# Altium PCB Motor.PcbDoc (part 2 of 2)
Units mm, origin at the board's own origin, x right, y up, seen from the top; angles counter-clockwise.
Board outline 48.64 x 60.2 mm, 4 copper layers (Top Layer, VCC, GND, Bottom Layer), stack 0.778 mm thick; 131 components, 120 nets, 670 pads, 289 vias.
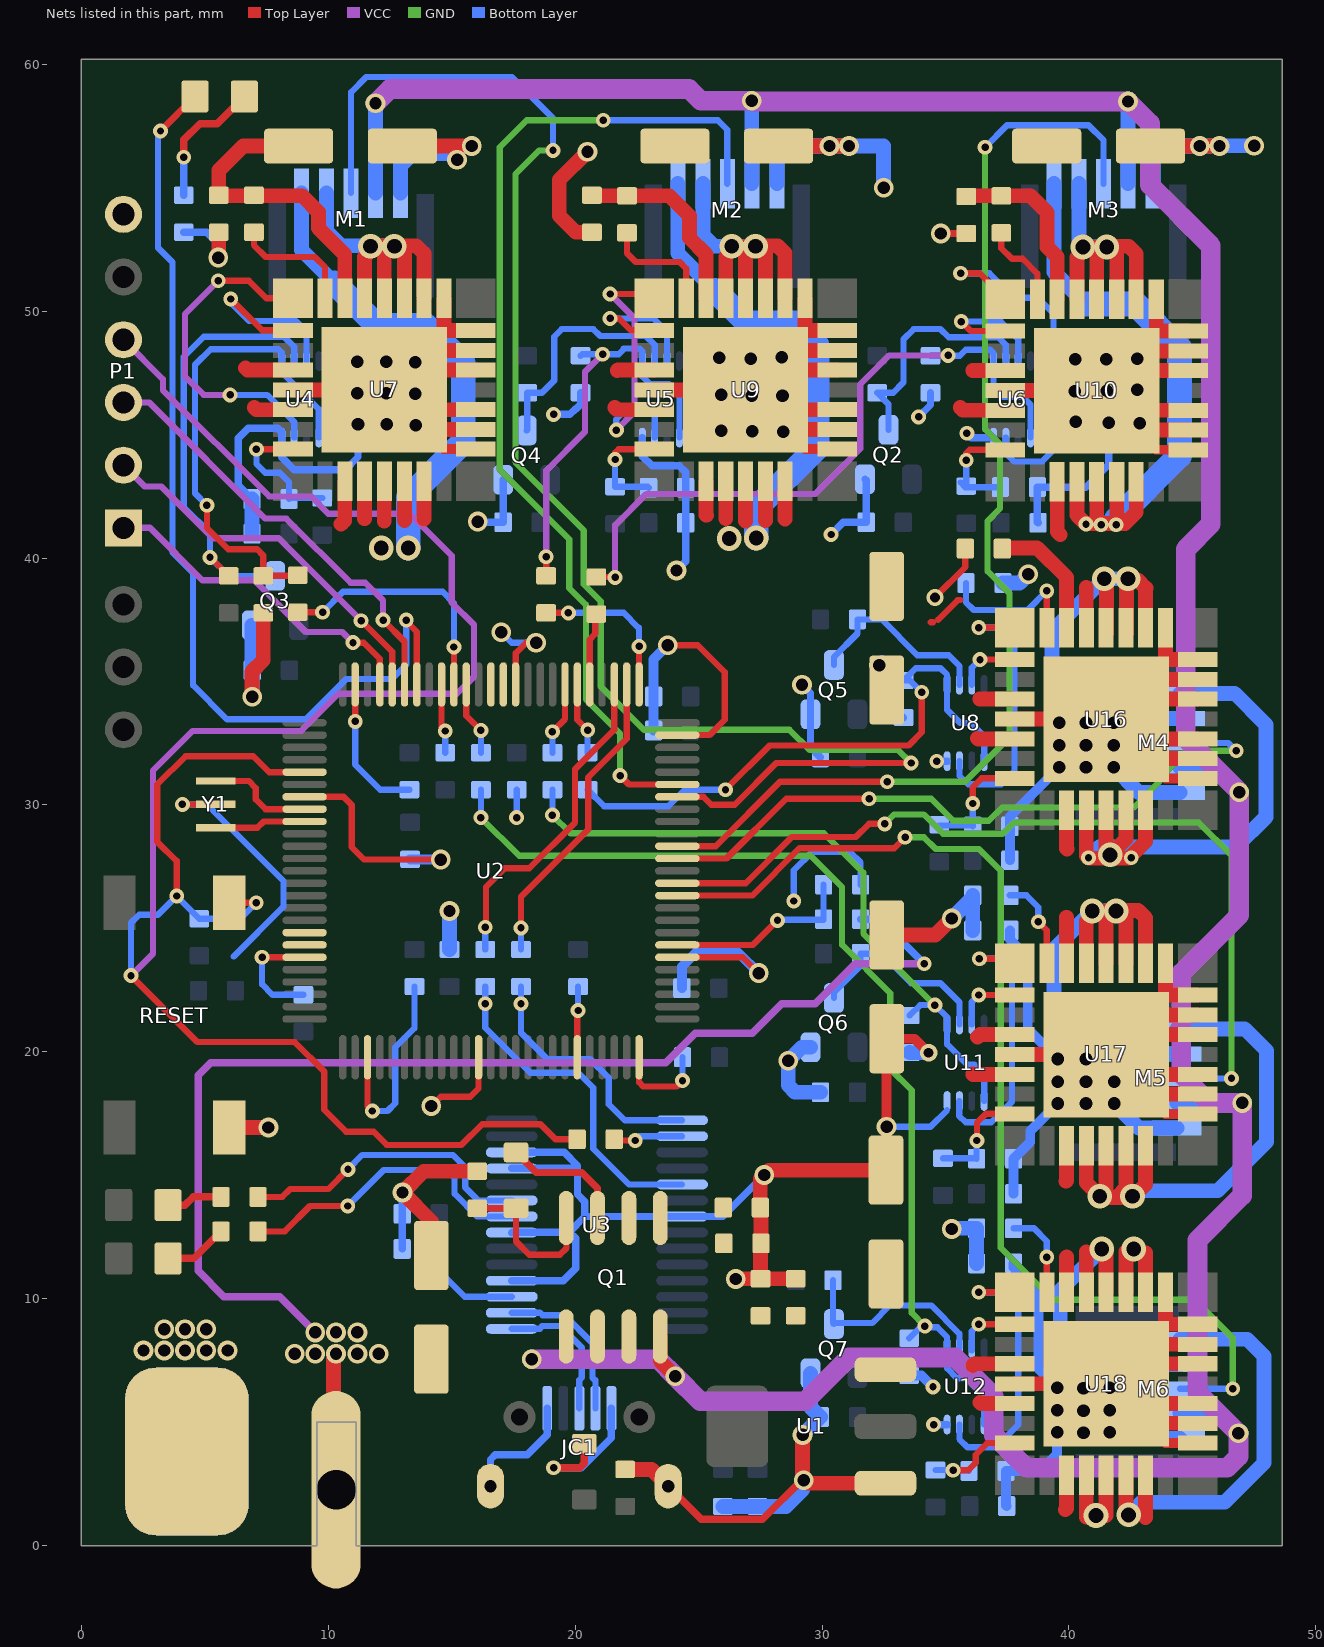
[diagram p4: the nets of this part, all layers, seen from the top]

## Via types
v1: diameter 0.6, hole 0.3, Top Layer to Bottom Layer, tented both sides, 138 vias
v2: diameter 0.8, hole 0.5, Top Layer to Bottom Layer, tented both sides, 75 vias
v3: diameter 1.016, hole 0.508, Top Layer to Bottom Layer, tented both sides, 53 vias
v4: diameter 1, hole 0.6, Top Layer to Bottom Layer, tented both sides, 21 vias
v5: diameter 0.7, hole 0.4, Top Layer to Bottom Layer, tented both sides, 2 vias

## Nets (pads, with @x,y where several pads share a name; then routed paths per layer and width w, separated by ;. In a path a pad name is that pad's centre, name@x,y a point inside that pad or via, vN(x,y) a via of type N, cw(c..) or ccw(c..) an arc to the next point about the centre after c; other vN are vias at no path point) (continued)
GND: C1.1 C2.1 C4.1 C5.1 C6.1 C7.1 C8.1 C9.1 C10.2 C11.2 C12.2 C13.2 C14.2 C16.1 C17.1 C18.1 C19.1 C20.1 C24.2 C25.2 C26.2 C27.1 C28.1 C29.1 C33.2 C34.2 C35.2 CP1.2 CP2.2 CP3.2 CP4.2 CP5.2 CP6.2 CP7.2 JC1.0 JC1.5 M1.1 M2.1 M3.1 M4.1 M5.1 M6.1 P1.6 pad.0 Q2.2 Q3.2 Q4.2 Q5.2 Q6.2 Q7.2 R2.1 R5.2 R15.1 R21.1 R22.1 R23.1 R24.1 R25.1 R26.1 R30.1 R31.1 R32.1 R33.1 R34.1 R35.1 R36.1 R37.1 R38.1 R42.1 R43.1 R44.1 RESET.1 U1.1 U2.11 U2.32 U2.62 U2.81 U2.99 U3.7 U3.18 U3.21 U3.25 U3.26 U4.4 U5.4 U6.4 U7.5 U7.18 U7.19 U7.20 U7.22 U7.23 U7.24 U7.26 U7.33 U8.4 U9.5 U9.18 U9.19 U9.20 U9.22 U9.23 U9.24 U9.26 U9.33 U10.5 U10.18 U10.19 U10.20 U10.22 U10.23 U10.24 U10.26 U10.33 U11.4 U12.4 U16.5 U16.18 U16.19 U16.20 U16.22 U16.23 U16.24 U16.26 U16.33 U17.5 U17.18 U17.19 U17.20 U17.22 U17.23 U17.24 U17.26 U17.33 U18.5 U18.18 U18.19 U18.20 U18.22 U18.23 U18.24 U18.26 U18.33 Y1.2 | length 395.7
  Top Layer w0.254: v1(4.089,30.023) Y1.2@5.436,30.023 ; U2.32@9.036,30.33 10.614,30.33 10.947,29.997 10.947,28.296 11.455,27.788 v2(14.554,27.788) ; v2(14.173,17.805) 14.554,18.186 15.748,18.186 16.086,18.525 U2.62@16.086,19.78 ; U2.11@17.586,34.88 17.586,36.154 18.009,36.576 v2(18.415,36.576) ; v2(23.749,36.474) 24.968,36.474 26.06,35.382 26.06,33.452 25.439,32.83 U2.99@24.136,32.83 ; U2.81@24.136,23.83 26.792,23.83 v2(27.432,23.19) ; v5(34.569,38.405) 35.801,39.636 C27.1@35.801,40.386
  Top Layer w0.3: JC1.0@23.768,2.407 25.108,1.067 27.584,1.067 v2@29.21,2.692 ; v2@34.798,53.162 v2(34.811,53.149) C18.1@35.839,53.149
  Top Layer w0.4: U7.33@13.868,45.212 14.668,44.412 U7.18@15.977,44.412 ; U9.33@28.499,45.212 29.299,44.412 U9.18@30.607,44.412 ; CP7.2@32.588,15.206 32.614,15.232 v2(32.614,16.967) CP6.2@32.614,20.531 33.748,20.531 v5(34.315,19.964) ; U10.33@42.723,45.187 43.523,44.387 U10.18@44.831,44.387 ; U18.33@43.104,4.953 43.904,4.153 U18.18@45.212,4.153 ; U17.33@43.104,18.288 43.904,17.488 U17.18@45.212,17.488 ; U16.33@43.904,31.077 U16.18@45.212,31.077
  Top Layer w0.6: v2@5.563,52.172 C19.1@5.563,53.2 ; RESET.1@5.984,16.938 v2(7.573,16.938) ; v2(6.921,34.38) 6.909,34.392 6.909,35.408 7.366,35.865 R24.1@7.366,37.782 ; U7.5@8.568,46.812 U7.33@12.268,46.812 ; CP3.2@12.997,56.693 v2(15.807,56.693) ; CP1.2@14.173,11.752 14.173,13.133 v2(13.005,14.302) 13.867,15.164 R2.1@16.027,15.164 ; U7.26@14.681,50.521 U7.33@14.681,49.225 ; U7.19@15.977,45.212 13.868,45.212 U7.33@13.068,46.012 ; U7.20@15.977,46.012 U7.33@13.068,46.012 ; U7.22@15.977,47.625 U7.33@13.081,47.625 ; U7.23@15.977,48.412 14.376,48.412 U7.33@14.122,48.666 ; U7.24@15.977,49.225 U7.33@14.681,49.225 ; v2(20.498,56.464) 19.355,55.321 19.355,53.873 20.029,53.2 C20.1@20.676,53.2 ; C17.1@22.022,3.087 23.088,3.087 JC1.0@23.768,2.407 ; U9.5@23.199,46.812 U9.33@26.899,46.812 U9.33@27.699,46.012 ; v2(26.5,10.8) 26.508,10.808 C7.1@27.508,10.808 ; U9.33@27.711,47.625 U9.22@30.607,47.625 ; CP4.2@28.237,56.693 v2(30.3,56.693) v2(31.09,56.693) ; U9.33@28.499,48.412 U9.23@30.607,48.412 ; C6.1@28.917,10.795 C6.1@28.931,10.808 C7.1@27.508,10.808 ; v2@29.21,2.692 v2(29.21,4.484) ; v2(29.261,2.642) 29.376,2.526 U1.1@32.566,2.526 ; U9.26@29.312,50.521 29.312,49.225 U9.24@30.607,49.225 ; U9.19@30.607,45.212 28.499,45.212 U9.33@27.699,46.012 ; U9.20@30.607,46.012 U9.33@27.699,46.012 ; CP7.2@32.588,15.206 27.856,15.206 v2(27.661,15.011) 27.496,14.847 C2.1@27.496,13.691 27.522,13.665 C1.1@27.522,12.243 27.508,12.229 C7.1@27.508,10.808 ; U10.5@37.423,46.787 U10.33@41.123,46.787 ; U18.5@37.804,6.553 U18.33@41.504,6.553 ; U17.5@37.804,19.888 U17.33@41.504,19.888 ; U16.5@37.804,33.477 U16.33@41.504,33.477 U16.33@42.304,32.677 ; U17.33@43.104,18.288 U17.19@45.212,18.288 ; U10.33@43.155,48.387 U10.23@44.831,48.387 ; U10.33@43.155,48.819 U10.33@43.536,49.2 ; CP2.2@43.299,56.693 v2(45.3,56.693) 45.72,56.693 45.727,56.7 v2@46.1,56.7 ; U10.26@43.536,50.495 U10.33@43.536,49.2 ; U18.26@43.917,10.262 U18.33@43.917,8.966 ; U17.26@43.917,23.597 43.917,22.301 U17.24@45.212,22.301 ; U16.26@43.917,37.186 U16.33@43.917,35.89 ; U10.19@44.831,45.187 42.723,45.187 U10.33@41.923,45.987 ; U10.20@44.831,45.987 U10.33@41.923,45.987 ; U10.22@44.831,47.6 41.935,47.6 U10.33@41.123,46.787 ; U10.24@44.831,49.2 U10.33@43.536,49.2 ; U18.19@45.212,4.953 43.104,4.953 U18.33@42.304,5.753 ; U18.20@45.212,5.753 U18.33@42.304,5.753 ; U18.22@45.212,7.366 U18.33@42.316,7.366 ; U18.23@45.212,8.153 U18.33@43.104,8.153 ; U18.24@45.212,8.966 U18.33@43.917,8.966 ; U17.20@45.212,19.088 42.304,19.088 U17.33@41.504,19.888 ; U17.22@45.212,20.701 U17.33@42.316,20.701 ; U17.23@45.212,21.488 43.104,21.488 U17.33@42.316,20.701 ; U16.19@45.212,31.877 43.104,31.877 U16.33@42.304,32.677 ; U16.20@45.212,32.677 U16.33@42.304,32.677 ; U16.22@45.212,34.29 42.316,34.29 U16.33@43.104,35.077 ; U16.23@45.212,35.077 U16.33@43.104,35.077 ; U16.24@45.212,35.89 U16.33@43.917,35.89 ; U7.33@12.268,46.812 U7.33@13.081,47.625 ; U7.33@12.268,46.812 U7.33@13.068,46.012 ; U7.33@13.081,47.625 U7.33@14.122,48.666 ; U7.33@14.122,48.666 U7.33@14.681,49.225 ; U10.33@41.123,46.787 U10.33@41.923,45.987 ; U18.33@41.504,6.553 U18.33@42.316,7.366 ; U18.33@41.504,6.553 U18.33@42.304,5.753 ; U17.33@41.504,19.888 U17.33@42.316,20.701 ; U18.33@42.316,7.366 U18.33@43.104,8.153 ; U18.33@43.104,8.153 U18.33@43.917,8.966 ; U16.33@43.104,35.077 U16.33@43.917,35.89
  Bottom Layer w0.254: v1(4.089,30.023) 5.08,30.023 8.179,26.924 8.179,25.869 6.172,23.863 ; v2(17,37) 17.424,36.576 v2(18.415,36.576) ; v1(17.628,29.489) C13.2@17.628,30.619 ; v1(28.854,26.111) 28.854,27.356 29.591,28.092 31.14,28.092 31.56,27.673 R15.1@31.56,26.772 ; v2@32.842,16.967 34.392,16.967 U11.4@35.064,17.64
  Bottom Layer w0.3: R5.2@4.14,53.2 5.068,53.2 5.537,52.73 v2(5.537,52.172) ; R31.1@6.909,42.393 6.35,42.951 6.35,44.856 6.756,45.263 7.95,45.263 8.115,45.098 U4.4@8.115,44.881 8.115,44.082 8.611,43.586 10.693,43.586 11.201,44.094 v3(11.201,45.415) ; C14.2@12.991,12.014 C16.1@12.991,13.437 12.991,14.288 v2(13.005,14.302) ; v2(16.053,41.478) 16.078,41.453 R25.1@17.081,41.453 17.084,41.456 Q4.2@17.084,43.171 ; JC1.0@16.568,2.407 16.568,3.487 16.764,3.683 18.055,3.683 18.868,4.496 JC1.5@18.868,5.559 ; U3.18@17.429,10.73 19.518,10.73 20.015,11.227 20.015,12.446 19.761,12.7 ; U3.21@17.429,12.68 17.449,12.7 19.761,12.7 ; U3.25@17.429,15.28 20.091,15.28 ; U3.26@17.429,15.93 19.554,15.93 20.091,15.392 20.091,14.224 20.391,13.924 20.391,13.33 ; v1(19.126,45.822) 19.787,45.822 20.015,46.05 ; 20.041,46.05 20.218,46.228 R26.1@20.218,46.697 ; U5.4@22.72,44.881 22.72,44.133 23.114,43.739 24.206,43.739 24.474,43.471 R32.1@24.474,42.85 C26.2@24.474,41.427 24.474,39.874 v2(24.1,39.5) ; v2(27.661,15.011) 25.979,13.33 U3.7@24.329,13.33 20.391,13.33 ; v2(29.185,34.874) 29.53,34.529 Q5.2@29.53,33.671 29.53,32.331 R33.1@29.933,31.928 ; v1(30.366,40.957) 30.861,41.453 R21.1@31.787,41.453 31.787,43.148 Q2.2@31.74,43.196 ; v2(32.309,35.662) 32.309,34.531 R34.1@33.299,33.54 ; v2@32.385,35.662 32.385,35.892 v2@32.422,35.929 ; v1(33.909,45.72) 34.392,46.203 R22.1@34.392,46.697 ; v1(34.518,4.902) U12.4@35.064,4.902 ; v1@34.57,31.775 U8.4@35.064,31.775 ; v1(35.865,45.06) 36.043,44.881 U6.4@36.944,44.881 ; C24.2@38.748,41.427 38.723,41.453 R30.1@38.723,42.875 40.691,42.875 41.605,43.79 v3(41.605,45.491) ; 19.761,12.7 20.391,13.33
  Bottom Layer w0.4: C10.2@13.31,27.8 13.322,27.788 v2(14.554,27.788) ; C8.1@23.177,33.02 C9.1@23.177,34.392 23.177,35.902 v2(23.749,36.474) ; C11.2@24.32,22.581 24.32,23.456 24.867,24.003 26.619,24.003 v2(27.432,23.19) ; R38.1@33.528,6.895 34.024,6.895 v1(34.493,6.426) ; R36.1@33.553,19.976 R36.1@33.818,19.976 ; C35.2@37.478,1.6 37.453,1.626 R44.1@37.453,3.023 38.837,3.023 39.522,3.708 v3(39.522,4.597) ; C28.1@37.605,24.917 37.605,24.548 38.329,23.825 38.329,20.93 v3(39.548,19.71) ; C33.2@37.605,27.762 R42.1@37.605,29.134 37.605,29.528 v3(39.599,31.521) ; C29.1@37.758,11.43 37.758,11.264 38.76,10.262 38.76,7.163 v3(39.522,6.401) ; C34.2@37.758,14.249 R43.1@37.758,15.672 38.43,16.344 38.43,16.789 v3(39.548,17.907)
  Bottom Layer w0.6: Q3.2@6.899,37.278 6.899,35.481 R23.1@6.921,35.458 v2(6.921,34.38) ; C25.2@6.909,40.993 R31.1@6.909,42.393 ; M1.1@12.929,54.788 12.929,55.905 13.411,56.388 15.24,56.388 15.215,56.363 v2(15.215,56.134) ; C12.2@14.91,24.143 v2(14.91,25.705) ; C4.1@25.984,1.587 C5.1@27.381,1.587 28.536,1.587 v2@29.21,2.261 ; M2.1@28.169,55.169 28.169,56.388 28.473,56.693 v2(30.3,56.693) v2(31.09,56.693) 32.493,56.693 32.493,55.007 v2(32.5,55) ; v2(29.21,4.484) R37.1@29.933,5.207 29.53,5.61 Q7.2@29.53,6.976 ; Q6.2@29.53,20.184 29.175,20.184 v2(28.626,19.634) 28.626,18.644 28.905,18.364 R35.1@29.933,18.364 ; R36.1@33.553,19.976 33.565,19.964 v5(34.315,19.964) ; v3(41.656,5.486) 42.799,4.343 M6.1@44.501,4.343 ; v3(41.808,31.521) 42.824,30.505 M4.1@44.501,30.505 ; v3(41.834,17.907) 42.824,16.916 M5.1@44.374,16.916 ; M3.1@43.409,55.169 43.409,56.185 43.917,56.693 v2(45.3,56.693) v2@45.72,56.693 ; v2(46.1,56.693) 46.107,56.7 v2(47.5,56.7)
  other v1: 34.646,31.775
  other v2: 2.515,7.899 3.353,7.899 4.191,7.899 5.055,7.899 5.918,7.899 3.353,8.763 4.191,8.763 5.055,8.763
  other v3: 40.589,4.572 41.656,4.597 40.589,5.461 39.522,5.486 40.589,6.375 41.656,6.401 40.691,17.907 39.548,18.796 40.691,18.796 41.834,18.796 40.691,19.71 40.691,31.521 39.599,32.41 40.691,32.41 41.808,32.41 39.599,33.325 40.691,33.325 41.808,33.325 28.423,45.11 27.178,45.136 25.908,45.161 13.538,45.39 12.37,45.415 42.875,45.466 40.284,45.517 27.153,46.584 28.397,46.584 25.908,46.609 13.513,46.66 11.176,46.685 12.344,46.685 40.234,46.761 41.529,46.787 42.774,46.812 13.513,47.93 11.176,47.955 12.344,47.955 40.259,48.057 41.504,48.057 27.102,48.082 42.774,48.082 25.832,48.108 28.372,48.133
IIC_SCL: U2.43
IIC_SDA: U2.44
M1A: M1.4 U7.27 U7.28 U7.29 U7.30 | length 14.6
  Top Layer w0.6: U7.30@11.468,50.521 11.468,52.21 11.913,52.654 v4@12.268,52.654 ; U7.29@12.268,50.521 v4@12.268,52.654 ; U7.28@13.081,50.521 v4@13.081,52.629 ; U7.27@13.868,50.521 13.868,52.349 13.564,52.654 v4@12.268,52.654
  Bottom Layer w0.6: M1.4@9.931,54.788 9.931,53.238 10.516,52.654 v4@12.268,52.654
  other v4: 11.709,52.629 12.675,52.629
M1B: M1.5 U7.12 U7.13 U7.14 U7.15 | length 25.4
  Top Layer w0.6: 11.468,41.592 U7.12@11.468,43.112 ; 12.268,41.504 U7.13@12.268,43.112 ; 13.081,41.529 U7.14@13.081,43.112 ; 13.868,41.58 U7.15@13.868,43.112
  Bottom Layer w0.6: M1.5@8.915,54.788 8.915,52.476 10.236,51.156
  Bottom Layer w1: 10.236,51.156 11.963,49.428 13.945,49.428 15.469,47.904 15.469,44.704 13.233,42.469 v4(13.233,40.411)
  other v4: 12.141,40.411
M2A: M2.4 U9.27 U9.28 U9.29 U9.30 | length 13.5
  Top Layer w0.6: U9.30@26.099,50.521 v4@26.099,52.21 ; U9.29@26.899,50.521 v4@26.899,52.629 ; v4@27.305,52.654 28.194,52.654 28.499,52.349 U9.27@28.499,50.521 ; U9.28@27.711,50.521 v4@27.711,52.629
  Bottom Layer w0.6: M2.4@25.171,55.169 25.171,53.086 25.629,52.629 v4(26.34,52.629) v4(27.305,52.629)
M2B: M2.5 U9.12 U9.13 U9.14 U9.15 | length 25.1
  Top Layer w0.6: 26.099,41.592 U9.12@26.099,43.112 ; 26.899,41.504 U9.13@26.899,43.112 ; 27.711,41.529 U9.14@27.711,43.112 ; 28.499,41.58 U9.15@28.499,43.112
  Bottom Layer w0.6: M2.5@24.155,55.169 24.155,52.349 25.654,50.851
  Bottom Layer w1: 25.654,50.851 26.975,49.53 28.88,49.53 29.794,48.616 29.794,44.475 27.33,42.012 v4(27.33,40.818)
  other v4: 26.238,40.792
M3A: M3.4 U10.27 U10.28 U10.29 U10.30 | length 12.6
  Top Layer w0.6: U10.30@40.323,50.495 v4@40.323,52.184 ; U10.29@41.123,50.495 v4@41.123,52.603 ; v4@41.529,52.629 42.418,52.629 42.723,52.324 U10.27@42.723,50.495 ; U10.28@41.935,50.495 v4@41.935,52.603
  Bottom Layer w0.6: M3.4@40.411,55.169 40.411,52.756 v4(40.564,52.603) v4(41.529,52.603)
M3B: M3.5 U10.12 U10.13 U10.14 U10.15 | length 26.7
  Top Layer w0.6: U10.12@40.323,43.087 40.323,41.745 40.665,41.402 v1@41.097,41.402 ; U10.13@41.123,43.087 41.123,41.427 v1@41.097,41.402 ; U10.14@41.935,43.087 41.935,41.732 42.266,41.402 ; U10.15@42.723,43.087 42.723,41.859 42.266,41.402 ; v1@41.097,41.402 42.266,41.402
  Bottom Layer w0.6: M3.5@39.395,55.169 39.395,51.587 40.691,50.292
  Bottom Layer w1: 40.691,50.292 42.697,50.292 44.475,48.514 44.475,44.145 v1@41.91,41.58
  other v1: 41.3,41.351 41.91,41.351 40.691,41.377
M4A: M4.4 U16.27 U16.28 U16.29 U16.30 | length 19.7
  Top Layer w0.6: U16.30@40.704,37.186 40.704,38.811 ; U16.29@41.516,36.957 v4@41.516,39.065 ; U16.28@42.329,36.957 v4@42.329,39.065 ; v4@42.812,39.091 43.116,38.786 ; U16.27@43.104,37.186 43.104,38.773
  Bottom Layer w0.6: v4(42.393,39.167) v4(41.427,39.167) 39.319,37.059 39.319,34.976 39.903,34.392 42.316,34.392 43.205,33.503 M4.4@44.501,33.503
M4B: M4.5 U16.12 U16.13 U16.14 U16.15 | length 25.3
  Top Layer w0.6: U16.12@40.704,29.777 40.704,27.953 v1(40.792,27.864) 40.818,27.838 41.504,27.838 U16.13@41.504,29.777 ; U16.14@42.316,29.777 42.316,28.626 v4(41.669,27.978) 41.808,27.838 42.418,27.838 43.104,28.524 U16.15@43.104,29.777
  Bottom Layer w0.6: v1(40.792,27.864) 41.224,28.296 46.761,28.296 47.981,29.515 47.981,33.249 46.711,34.519 M4.5@44.501,34.519
  other v1: 42.52,27.864
M5A: M5.4 U17.27 U17.28 U17.29 U17.30 | length 20.6
  Top Layer w0.6: U17.30@40.704,23.597 v4@40.704,25.286 ; U17.29@41.504,23.597 v4@41.504,25.705 ; v4@41.91,25.73 42.799,25.73 43.104,25.425 U17.27@43.104,23.597 ; U17.28@42.316,23.597 v4@42.316,25.705
  Bottom Layer w0.6: v4(41.91,25.705) v4(40.945,25.705) 39.395,24.155 39.395,21.361 39.929,20.828 41.885,20.828 42.774,19.939 ; 42.774,19.914 M5.4@44.374,19.914
M5B: M5.5 U17.12 U17.13 U17.14 U17.15 | length 24
  Top Layer w0.6: U17.12@40.704,16.188 40.704,14.694 v4(41.25,14.148) ; v4@41.25,14.097 41.91,14.097 ; v4@41.504,14.402 U17.13@41.504,16.188 ; U17.14@42.316,16.188 42.316,14.503 41.91,14.097 ; U17.15@43.104,16.188 43.104,14.63 42.57,14.097 41.91,14.097
  Bottom Layer w0.6: v4(42.57,14.148) 42.799,14.376 46.025,14.376 48.006,16.358 48.006,20.041 47.117,20.93 M5.5@44.374,20.93
M6A: M6.4 U18.27 U18.28 U18.29 U18.30 | length 15.9
  Top Layer w0.6: U18.30@40.704,10.262 40.704,11.887 ; U18.29@41.504,10.262 v4@41.504,11.887 ; U18.28@42.316,10.262 v4@42.316,11.913 ; U18.27@43.104,10.262 43.104,11.862
  Bottom Layer w0.6: v4(41.326,12.014) 39.649,10.338 39.649,8.738 40.208,8.179 42.291,8.179 43.129,7.341 M6.4@44.501,7.341
  other v4: 42.621,12.014
M6B: M6.5 U18.12 U18.13 U18.14 U18.15 | length 21.1
  Top Layer w0.6: v4@40.704,1.156 U18.12@40.704,2.853 ; v4@41.504,1.214 U18.13@41.504,2.853 ; v4@42.316,1.164 U18.14@42.316,2.853 ; 43.104,1.135 U18.15@43.104,2.853
  Bottom Layer w0.6: v4(42.418,1.245) 42.926,1.753 46.304,1.753 47.904,3.353 47.904,7.671 47.219,8.357 M6.5@44.501,8.357
  other v4: 41.097,1.219
MCU-RX: R51.1 U2.2 | length 12.5
  Top Layer w0.254: v1(17.805,25.019) 17.805,26.289 20.523,29.007 20.523,31.115 22.086,32.678 U2.2@22.086,34.88
  Bottom Layer w0.254: R51.1@17.805,24.143 v1(17.805,25.019)
MCU-TX: R52.1 U2.3 | length 13.2
  Top Layer w0.254: v1@16.383,25.298 16.383,26.67 17.145,27.432 18.136,27.432 19.99,29.286 19.99,31.445 21.586,33.042 U2.3@21.586,34.88
  Bottom Layer w0.254: R52.1@16.358,24.143 v1(16.358,25.044)
NetC14_1: C14.1 U3.17 | length 4.3
  Bottom Layer w0.254: C14.1@14.491,12.014 14.491,11.112 15.523,10.08 U3.17@17.429,10.08
NetC15_1: C15.1 U3.2 | length 2.8
  Top Layer w0.254: C15.1@21.578,16.459 21.629,16.408 v1(22.428,16.408)
  Bottom Layer w0.254: v1(22.428,16.408) 22.6,16.58 U3.2@24.329,16.58
NetC21_2: C21.2 U10.32 | length 3.5
  Top Layer w0.254: C21.2@37.262,53.174 37.262,52.553 37.694,52.121 38.125,52.121 38.723,51.524 U10.32@38.723,50.495
NetC22_2: C22.2 U7.32 | length 5
  Top Layer w0.254: C22.2@6.985,53.174 6.985,52.68 7.468,52.197 9.449,52.197 9.868,51.778 U7.32@9.868,50.521
NetC23_2: C23.2 U9.32 | length 4.7
  Top Layer w0.254: C23.2@22.098,53.174 22.098,52.349 22.454,51.994 24.232,51.994 24.499,51.727 U9.32@24.499,50.521
NetC30_2: C30.2 U16.32 | length 6
  Top Layer w0.254: U16.32@39.104,37.186 v1(39.104,38.672)
  Bottom Layer w0.254: C30.2@35.826,38.989 35.826,38.215 36.144,37.897 38.329,37.897 v1(39.104,38.672)
NetC31_2: C31.2 U17.32 | length 3.8
  Top Layer w0.254: v1(38.76,25.273) 39.104,24.93 U17.32@39.104,23.597
  Bottom Layer w0.254: C31.2@37.605,26.34 38.278,26.34 38.76,25.857 v1(38.76,25.273)
NetC32_2: C32.2 U18.32 | length 3.8
  Top Layer w0.254: U18.32@39.104,10.262 v1(39.104,11.684)
  Bottom Layer w0.254: C32.2@37.758,12.852 38.583,12.852 39.104,12.331 v1(39.104,11.684) v1@39.014,11.773
NetD1_2: D1.2 Q1.4 R2.2 | length 6.5
  Top Layer w0.254: R2.2@16.027,13.664 D1.2@17.602,13.665 D1.2@17.602,13.665 17.602,12.319 18.136,11.786 19.38,11.786 19.647,12.052 19.647,13.259 Q1.4@19.634,13.271
NetLED1_1: LED1.1 R5.1 | length 5.4
  Top Layer w0.3: v1(4.14,56.236) 4.14,56.94 4.8,57.6 5.5,57.6 LED1.1@6.6,58.7
  Bottom Layer w0.3: R5.1@4.14,54.7 v1(4.14,56.236)
NetLED2_1: LED2.1 R7.1 | length 2.3
  Top Layer w0.3: LED2.1@3.51,13.79 4.189,13.79 4.521,14.122 R7.1@5.651,14.122
NetLED3_1: LED3.1 R9.1 | length 2.6
  Top Layer w0.3: LED3.1@3.51,11.631 4.557,11.631 R9.1@5.651,12.725
NetQ2_3: Q2.3 R47.1 U6.6 | length 9.9
  Bottom Layer w0.254: Q2.3@32.69,45.196 32.69,46.24 R47.1@32.233,46.697 32.88,46.697 33.299,47.117 33.299,48.87 33.706,49.276 34.798,49.276 35.128,48.946 37.135,48.946 37.444,48.637 U6.6@37.444,47.981
NetQ3_3: Q3.3 R45.1 U4.6 | length 18.2
  Top Layer w0.254: v1(5.207,40.03) 5.22,40.03 R45.1@5.969,39.282
  Bottom Layer w0.254: Q3.3@7.849,39.278 5.96,39.278 v1(5.207,40.03) 5.207,40.996 4.14,42.062 4.14,48.158 4.953,48.971 8.204,48.971 8.615,48.561 U4.6@8.615,47.981
NetQ4_3: Q4.3 R46.1 U5.6 | length 9.7
  Bottom Layer w0.254: Q4.3@18.034,45.171 18.059,45.196 R46.1@18.059,46.697 18.656,46.697 19.152,47.193 19.152,48.971 19.456,49.276 20.726,49.276 21.006,48.997 22.86,48.997 23.22,48.637 U5.6@23.22,47.981
NetQ5_3: Q5.3 R48.1 U8.6 | length 7.9
  Bottom Layer w0.254: Q5.3@30.48,35.671 30.48,35.992 31.433,36.945 R48.1@31.433,37.516 32.41,37.516 33.858,36.068 35.128,36.068 35.564,35.632 U8.6@35.564,34.875
NetQ6_3: Q6.3 R49.1 U11.6 | length 8
  Bottom Layer w0.254: Q6.3@30.48,22.184 30.48,22.403 31.56,23.483 R49.1@31.56,23.978 32.41,23.978 33.604,22.784 34.798,22.784 35.564,22.018 U11.6@35.564,21.108
NetQ7_3: Q7.3 R50.1 U12.6 | length 8.2
  Bottom Layer w0.254: R50.1@30.443,10.744 30.443,9.013 Q7.3@30.48,8.976 ; Q7.3@30.517,9.013 32.025,9.013 32.741,9.728 34.417,9.728 35.564,8.581 U12.6@35.564,8.002
NetR3_1: R3.1 U2.75 | length 3.9
  Top Layer w0.254: U2.75@22.586,19.78 22.586,18.765 22.758,18.593 24.105,18.593 v1(24.345,18.833)
  Bottom Layer w0.254: v1(24.345,18.833) R3.1@24.345,19.787
NetR4_1: R4.1 U2.24 | length 5.9
  Top Layer w0.254: v1(11.086,33.387) U2.24@11.086,34.88
  Bottom Layer w0.254: v1(11.086,33.387) 11.086,31.637 12.104,30.619 R4.1@13.284,30.619
NetR6_1: R6.1 U2.53 | length 8.4
  Top Layer w0.254: U2.53@11.586,19.78 11.586,17.802 v1(11.786,17.602)
  Bottom Layer w0.254: v1(11.786,17.602) 12.395,17.602 12.712,17.919 12.712,20.18 13.487,20.955 R6.1@13.487,22.643
NetR7_2: R7.2 U3.23 | length 12.2
  Top Layer w0.254: R7.2@7.151,14.122 8.128,14.122 8.446,14.441 9.996,14.441 v1(10.795,15.24)
  Bottom Layer w0.254: v1(10.795,15.24) 11.379,15.824 15.037,15.824 15.545,15.316 15.545,14.503 16.068,13.98 U3.23@17.429,13.98
NetR9_2: R9.2 U3.22 | length 12.5
  Top Layer w0.254: R9.2@7.151,12.725 8.23,12.725 9.258,13.754 v1(10.782,13.754)
  Bottom Layer w0.254: v1(10.782,13.754) 12.242,15.214 14.784,15.214 15.113,14.884 15.113,14.248 16.032,13.33 U3.22@17.429,13.33
NetR10_1: R10.1 U2.45 | length 4.7
  Top Layer w0.254: v1(7.315,23.83) U2.45@9.036,23.83
  Bottom Layer w0.254: v1(7.315,23.83) 7.315,22.733 7.734,22.315 R10.1@8.992,22.315
NetR11_1: R11.1 U2.7 | length 3
  Top Layer w0.254: v1(19.075,32.969) 19.586,33.48 U2.7@19.586,34.88
  Bottom Layer w0.254: R11.1@19.075,32.119 v1(19.075,32.969)
NetR12_1: R12.1 U2.6 | length 2.9
  Top Layer w0.254: U2.6@20.086,34.88 20.086,33.457 v1(20.511,33.033)
  Bottom Layer w0.254: R12.1@20.498,32.119 20.498,33.02 v1(20.511,33.033)
NetR13_1: R13.1 U2.5 | length 3
  Top Layer w0.254: U2.5@20.586,34.88 20.586,36.702 20.816,36.932 20.816,37.694 R13.1@20.853,37.731
NetR16_1: R16.1 U2.17 | length 2.8
  Top Layer w0.254: U2.17@14.586,34.88 14.586,33.14 v1(14.732,32.995)
  Bottom Layer w0.254: R16.1@14.732,32.119 v1(14.732,32.995)
NetR17_2: R17.2 U2.16 | length 10.2
  Top Layer w0.254: R17.2@8.763,37.807 v1(9.767,37.807) ; U2.16@15.086,34.88 15.086,36.397 v1(15.088,36.398)
  Bottom Layer w0.254: v1(9.767,37.807) 10.593,38.633 14.63,38.633 15.088,38.176 v1(15.088,36.398)
NetR18_2: R18.2 U2.15 | length 3
  Top Layer w0.254: U2.15@15.586,34.88 15.586,33.614 v1(16.18,33.02)
  Bottom Layer w0.254: R18.2@16.18,32.119 v1(16.18,33.02)
NetR19_1: R19.1 U2.70 | length 2.8
  Top Layer w0.254: U2.70@20.086,19.78 20.086,21.646 v1(20.117,21.677)
  Bottom Layer w0.254: v1@20.117,21.793 R19.1@20.117,22.643
NetR20_1: R20.1 U2.1 | length 6.3
  Top Layer w0.254: R20.1@18.821,37.782 v1(19.722,37.782) ; U2.1@22.586,34.88 v1(22.586,36.424)
  Bottom Layer w0.254: v1(19.722,37.782) 21.965,37.782 22.561,37.186 ; v1(22.586,36.424) 22.586,37.186
NetR27_2: R27.2 R30.2 U10.8 | length 4.5
  Top Layer w0.254: v1(35.839,43.967) 35.839,44.247 35.979,44.387 U10.8@37.423,44.387
  Bottom Layer w0.254: R27.2@35.611,43.066 35.763,42.914 35.802,42.875 R30.2@37.147,42.875 ; R27.2@35.839,42.99 v1(35.839,43.967)
NetR28_2: R28.2 R31.2 U7.8 | length 5.8
  Top Layer w0.254: v1(7.087,44.412) U7.8@8.568,44.412
  Bottom Layer w0.254: v1(7.087,44.412) 7.087,43.815 7.442,43.459 8.026,43.459 8.409,43.077 R31.2@8.409,42.393 8.448,42.431 R28.2@9.754,42.431
NetR29_2: R29.2 R32.2 U9.8 | length 4.4
  Top Layer w0.254: v1(21.615,43.993) 21.615,44.272 21.755,44.412 U9.8@23.199,44.412
  Bottom Layer w0.254: v1(21.615,43.993) R29.2@21.615,42.889 22.935,42.889 R32.2@22.974,42.85
NetR39_2: R39.2 R42.2 U16.8 | length 4.8
  Top Layer w0.254: v1(36.105,30.062) 36.105,30.721 36.462,31.077 U16.8@37.804,31.077
  Bottom Layer w0.254: R39.2@34.747,29.173 36.067,29.173 R42.2@36.105,29.134 v1(36.105,30.062)
NetR40_2: R40.2 R43.2 U17.8 | length 4.5
  Top Layer w0.254: v1(36.271,16.408) 36.271,17.12 36.64,17.488 U17.8@37.804,17.488
  Bottom Layer w0.254: R40.2@34.9,15.685 36.244,15.685 R43.2@36.258,15.672 v1@36.258,16.408
NetR41_2: R41.2 R44.2 U18.8 | length 4.5
  Top Layer w0.254: v1(35.306,3.048) 35.916,3.048 36.22,3.353 36.22,3.683 36.691,4.153 U18.8@37.804,4.153
  Bottom Layer w0.254: R41.2@34.595,3.061 35.914,3.061 R44.2@35.953,3.023
NetR51_2: R51.2 U3.1 | length 10.5
  Bottom Layer w0.254: R51.2@17.805,22.643 v1(17.805,21.946) 17.805,20.777 18.872,19.71 20.599,19.71 21.361,18.948 21.361,17.882 22.013,17.23 U3.1@24.329,17.23
NetR52_2: R52.2 U3.5 | length 13.7
  Bottom Layer w0.254: R52.2@16.358,22.643 v1(16.358,21.946) 16.358,20.98 18.186,19.152 20.117,19.152 20.726,18.542 20.726,16.078 22.175,14.63 U3.5@24.329,14.63
NetU2_33: U2.33 Y1.3 | length 4.3
  Top Layer w0.254: Y1.3@5.436,30.973 6.772,30.973 7.061,30.683 7.061,30.226 7.457,29.83 U2.33@9.036,29.83
NetU2_34: U2.34 Y1.1 | length 3.7
  Top Layer w0.254: Y1.1@5.436,29.073 7.127,29.073 7.385,29.33 U2.34@9.036,29.33
NetU4_3: U4.3 U7.1 | length 13.6
  Top Layer w0.254: v1(5.537,51.232) 6.782,51.232 7.493,50.521 U7.1@8.568,50.521
  VCC w0.254: v1@5.588,51.232 v1(5.537,51.232) 4.191,49.886 4.191,47.371 4.953,46.609 v1(6.02,46.609)
  Bottom Layer w0.254: v1(6.02,46.609) 7.518,46.609 8.615,45.513 U4.3@8.615,44.881
NetU4_7: U4.7 U7.2 | length 8
  Top Layer w0.254: v1(6.045,50.495) 7.315,49.225 U7.2@8.568,49.225
  Bottom Layer w0.254: v1(6.045,50.495) 6.045,50.343 6.782,49.606 8.687,49.606 9.115,49.178 U4.7@9.115,47.981
NetU5_3: U5.3 U9.1 | length 11.1
  Top Layer w0.254: v1(21.412,50.698) 23.021,50.698 U9.1@23.199,50.521
  VCC w0.254: v1(21.412,50.698) 22.403,49.708 22.403,45.923 v1(21.666,45.187)
  Bottom Layer w0.254: v1(21.666,45.187) 21.666,45.618 21.971,45.923 23.038,45.923 23.22,45.741 U5.3@23.22,44.881
NetU5_7: U5.7 U9.2 | length 5.7
  Top Layer w0.254: v1(21.412,49.708) 21.768,49.708 22.25,49.225 U9.2@23.199,49.225
  Bottom Layer w0.254: v1(21.412,49.708) 23.165,49.708 23.72,49.153 U5.7@23.72,47.981
NetU6_3: U6.3 U10.1 | length 15.1
  Top Layer w0.254: v1(35.611,51.537) 36.381,51.537 U10.1@37.423,50.495
  Bottom Layer w0.254: v1(35.611,51.537) 36.779,51.537 37.77,50.546 38.735,50.546 39.37,49.911 39.37,44.374 38.913,43.917 37.77,43.917 37.444,44.243 U6.3@37.444,44.881
NetU6_7: U6.7 U10.2 | length 5.4
  Top Layer w0.254: v1(35.636,49.581) 36.017,49.2 U10.2@37.423,49.2
  Bottom Layer w0.254: v1(35.636,49.581) 37.236,49.581 37.944,48.874 U6.7@37.944,47.981
NetU8_3: U8.3 U16.1 | length 11.7
  Top Layer w0.254: v1(36.347,37.186) U16.1@37.804,37.186
  Bottom Layer w0.254: U8.3@35.564,31.775 35.564,31.187 35.916,30.836 37.262,30.836 37.795,31.369 37.795,36.881 37.49,37.186 v1(36.347,37.186)
NetU8_7: U8.7 U16.2 | length 2.6
  Top Layer w0.254: v1(36.398,35.89) U16.2@37.804,35.89
  Bottom Layer w0.254: U8.7@36.064,34.875 36.064,35.556 v1(36.398,35.89)
NetU11_3: U11.3 U17.1 | length 11.5
  Top Layer w0.254: v1(36.373,23.774) 37.626,23.774 U17.1@37.804,23.597
  Bottom Layer w0.254: U11.3@35.564,18.008 35.56,18.004 35.56,17.399 35.814,17.145 36.855,17.145 37.694,17.983 37.694,23.317 37.236,23.774 v1(36.373,23.774)
NetU11_7: U11.7 U17.2 | length 2.8
  Top Layer w0.254: v1(36.347,22.301) U17.2@37.804,22.301
  Bottom Layer w0.254: U11.7@36.064,21.108 36.064,22.018 v1(36.347,22.301)
NetU12_3: U12.3 U18.1 | length 11.7
  Top Layer w0.254: v1(36.347,10.262) U18.1@37.804,10.262
  Bottom Layer w0.254: U12.3@35.564,4.902 35.564,4.314 35.89,3.988 37.033,3.988 37.948,4.902 37.948,9.931 37.617,10.262 v1(36.347,10.262)
NetU12_7: U12.7 U18.2 | length 2.6
  Top Layer w0.254: v1(36.347,8.966) U18.2@37.804,8.966
  Bottom Layer w0.254: U12.7@36.064,7.9 36.064,8.683 v1(36.347,8.966)
POT_A: M1.3 U2.94 | length 62.8
  Top Layer w0.254: U2.94@24.136,30.33 25.194,30.33 25.51,30.014 26.458,30.014 28.143,31.699 v1(33.604,31.699)
  GND w0.254: v1(19.101,56.515) 18.542,56.515 17.577,55.55 17.577,43.891 20.345,41.123 20.345,38.938 21.031,38.252 21.031,34.798 22.784,33.045 28.677,33.045 29.489,32.233 33.071,32.233 v1(33.604,31.699)
  Bottom Layer w0.254: M1.3@10.922,54.788 10.922,58.877 11.532,59.487 17.424,59.487 19.101,57.81 v1(19.101,56.515)
POT_B: M2.3 U2.95 | length 42
  Top Layer w0.254: v1(21.819,31.191) 22.179,30.83 U2.95@24.136,30.83
  GND w0.254: v1(21.133,57.734) 18.034,57.734 16.942,56.642 16.942,43.586 19.761,40.767 19.761,38.786 20.434,38.113 20.434,34.277 21.819,32.893 v1(21.819,31.191)
  Bottom Layer w0.254: v1(21.133,57.734) 25.781,57.734 26.162,57.353 M2.3@26.162,55.169
POT_C: M3.3 U2.90 | length 47.2
  Top Layer w0.254: U2.90@24.136,28.33 25.689,28.33 28.296,30.937 v1(32.639,30.937)
  GND w0.254: v1(32.639,30.937) 35.789,30.937 37.592,32.741 37.592,38.583 36.703,39.472 36.703,41.504 37.211,42.012 37.211,44.602 36.601,45.212 v1(36.601,56.642)
  Bottom Layer w0.254: v1(36.601,56.642) 37.49,57.531 40.792,57.531 41.402,56.921 M3.3@41.402,55.169
POT_D: M4.3 U2.89 | length 27.7
  Top Layer w0.254: U2.89@24.136,27.83 26.129,27.83 28.55,30.251 v1(31.902,30.251)
  GND w0.254: v1(31.902,30.251) 34.417,30.251 35.306,29.362 36.754,29.362 37.287,29.896 42.621,29.896 43.663,30.937 43.663,31.064 44.793,32.194 v1(46.774,32.194)
  Bottom Layer w0.254: M4.3@44.501,32.512 46.457,32.512 v1(46.774,32.194)
POT_E: M5.3 U2.87 | length 35.9
  Top Layer w0.254: U2.87@24.136,26.83 26.907,26.83 28.778,28.702 31.369,28.702 31.902,29.235 v1(32.537,29.235)
  GND w0.254: v1(32.537,29.235) 32.918,29.616 34.112,29.616 34.9,28.829 37.313,28.829 37.77,29.286 45.263,29.286 46.584,27.965 v1(46.584,18.923)
  Bottom Layer w0.254: M5.3@44.374,18.923 v1(46.584,18.923)
POT_F: M6.3 U2.86 | length 45
  Top Layer w0.254: U2.86@24.136,26.33 27.169,26.33 29.083,28.245 32.918,28.245 v1(33.363,28.689)
  GND w0.254: v1(33.363,28.689) 34.125,28.689 34.595,28.219 36.347,28.219 37.236,27.33 37.236,12.065 39.345,9.957 45.085,9.957 46.634,8.407 v1(46.634,6.35)
  Bottom Layer w0.254: M6.3@44.501,6.35 v1(46.634,6.35)
PWM_A: R17.1 R24.2 U4.1 U4.5 | length 19.7
  Top Layer w0.254: v1(5.08,42.139) 5.08,41.224 5.944,40.361 7.112,40.361 7.366,40.107 R24.2@7.366,39.282 8.738,39.282 R17.1@8.763,39.307
  Bottom Layer w0.254: v1(5.08,42.139) 4.597,42.621 4.597,47.828 5.232,48.463 7.976,48.463 8.115,48.324 U4.5@8.115,47.981 8.115,47.537 9.615,46.037 U4.1@9.615,44.881
PWM_B: R20.2 R26.2 U5.1 U5.5 | length 17.1
  Top Layer w0.254: R20.2@18.821,39.282 v1(18.821,40.056)
  VCC w0.254: v1(18.821,40.056) 18.821,43.536 20.396,45.11 20.396,47.549 v1(21.107,48.26)
  Bottom Layer w0.254: R26.2@20.218,48.197 20.281,48.26 v1(21.107,48.26) 21.768,48.26 21.971,48.463 ; 21.971,48.489 22.606,48.489 22.72,48.375 U5.5@22.72,47.981 22.72,47.359 23.038,47.041 23.8,47.041 24.22,46.621 U5.1@24.22,44.881
PWM_C: R13.2 R22.2 U6.1 U6.5 | length 28
  Top Layer w0.254: R13.2@20.853,39.231 v1@21.629,39.231
  VCC w0.254: v1(21.615,39.218) 21.615,41.326 22.885,42.596 29.718,42.596 31.547,44.425 31.547,47.041 32.715,48.209 v1(35.103,48.209)
  Bottom Layer w0.254: R22.2@34.392,48.197 35.573,48.197 35.814,48.438 36.805,48.438 36.944,48.299 U6.5@36.944,47.981 36.944,46.902 37.313,46.533 38.125,46.533 38.444,46.215 U6.1@38.444,44.881
PWM_D: R12.2 R34.2 U8.1 U8.5 | length 24.1
  Top Layer w0.254: v1(26.086,30.619) 27.877,32.41 33.503,32.41 34.036,32.944 v1(34.036,34.569)
  Bottom Layer w0.254: R12.2@20.498,30.619 21.17,29.947 23.774,29.947 24.447,30.619 v1(26.086,30.619) ; v1(34.036,34.569) 33.565,35.04 R34.2@33.299,35.04 33.794,35.535 34.798,35.535 35.064,35.269 U8.5@35.064,34.875 35.064,33.846 35.585,33.325 36.017,33.325 36.564,32.778 U8.1@36.564,31.775
PWM_E: R11.2 R36.2 U11.1 U11.5 | length 27.2
  GND w0.254: v1(19.075,29.591) 19.812,28.854 30.074,28.854 31.674,27.254 31.674,24.79 v1(34.569,21.895)
  Bottom Layer w0.254: v1(19.075,29.591) R11.2@19.075,30.619 ; R36.2@33.553,21.476 33.972,21.895 v1(34.569,21.895) 35.064,21.4 U11.5@35.064,21.108 35.064,20.308 35.89,19.482 36.17,19.482 36.564,19.087 U11.1@36.564,18.008
PWM_F: R18.1 R38.2 U12.1 U12.5 | length 42.4
  GND w0.254: v1(16.18,29.489) 17.729,27.94 29.54,27.94 30.81,26.67 30.81,24.333 32.766,22.377 32.766,19.304 33.63,18.44 33.63,9.423 v1(34.163,8.89)
  Bottom Layer w0.254: v1(16.18,29.489) R18.1@16.18,30.619 ; R38.2@33.528,8.395 33.972,8.839 34.671,8.839 35.064,8.446 U12.5@35.064,8.002 35.064,7.176 35.458,6.782 35.814,6.782 36.564,6.032 U12.1@36.564,4.902
RESET: C15.2 P1.4 R1.1 RESET.2 U2.30 | length 89.3
  Top Layer w0.254: v1(2.007,23.089) 4.699,20.396 8.636,20.396 9.83,19.202 9.83,17.653 10.719,16.764 11.836,16.764 12.37,16.231 15.392,16.231 16.231,17.069 18.593,17.069 19.202,16.459 C15.2@20.078,16.459 ; v1(3.861,26.314) 3.861,27.737 3.835,27.737 3.073,28.499 3.073,30.835 4.217,31.979 6.96,31.979 7.608,31.33 U2.30@9.036,31.33 ; RESET.2@5.984,26.038 v1(7.083,26.038) ; C15.2@19.945,16.326 C15.2@20.078,16.193
  VCC w0.254: P1.4@1.702,48.844 3.3,47.246 3.3,46.8 7.6,42.5 9.3,42.5 10,41.8 13.3,41.8 15,40.1 15,38.2 15.9,37.3 15.9,35.2 15.2,34.5 10.4,34.5 8.9,33 4.5,33 2.9,31.4 2.9,23.982 v1(2.007,23.089)
  Bottom Layer w0.254: v1(2.007,23.089) 2.007,25.222 2.337,25.552 3.099,25.552 v1(3.861,26.314) 3.861,26.302 R1.1@4.775,25.388 6.147,25.388 6.172,25.363 6.407,25.363 v1(7.083,26.038)
SPI_MISO: P1.1 U2.22 | length 13.6
  Top Layer w0.254: v1(10.998,36.576) 11.43,36.576 12.086,35.92 U2.22@12.086,34.88
  VCC w0.254: P1.1@1.702,41.224 2.776,41.224 4.9,39.1 7,39.1 9.092,37.008 10.566,37.008 v1(10.998,36.576)
SPI_MOSI: P1.2 U2.21 | length 15.3
  Top Layer w0.254: v1(11.328,37.465) 12.586,36.207 U2.21@12.586,34.88
  VCC w0.254: P1.2@1.702,43.764 2.566,42.9 3.226,42.9 5.326,40.8 7.993,40.8 v1(11.328,37.465)
SPI_SCK: P1.3 U2.20 | length 17.6
  Top Layer w0.254: v1(12.217,37.49) 13.086,36.622 U2.20@13.086,34.88
  VCC w0.254: P1.3@1.702,46.304 2.743,46.304 7.447,41.6 8.3,41.6 10.9,39 11.5,39 12.217,38.283 v1(12.217,37.49)
UART2_RX: U2.12
UART2_TX: U2.13
USB_5V: D2.2 JC1.1 | length 6.2
  Top Layer w0.3: v1(19.126,3.15) 20.193,3.15 20.371,3.327 D2.2@20.371,4.127
  Bottom Layer w0.3: v1(19.126,3.15) 20.244,3.15 21.468,4.373 JC1.1@21.468,5.559
USBDM: JC1.2 U3.16 | length 6.5
  Bottom Layer w0.254: U3.16@17.429,9.43 18.575,9.43 18.677,9.328 19.577,9.328 20.701,8.204 20.701,6.797 20.792,6.706 ; JC1.2@20.818,5.559 20.818,6.706
USBDP: JC1.3 U3.15 | length 5.7
  Bottom Layer w0.254: U3.15@17.429,8.78 18.575,8.78 ; 18.575,8.805 18.667,8.896 19.398,8.896 20.269,8.025 20.269,6.807 20.168,6.706 JC1.3@20.168,5.559
VIN: CP1.1 M1.2 M2.2 M3.2 M4.2 M5.2 M6.2 pad.1 Q1.5 Q1.6 Q1.7 Q1.8 R14.2 | length 195.7
  Top Layer w0.6: 10.211,6.274 v2@10.211,7.518 ; Q1.8@23.444,8.471 23.444,7.468 v2(24.054,6.858)
  VCC w0.3: v2(9.474,8.636) 8.026,10.084 7.264,10.084 5.766,10.084 4.724,11.125 4.724,19.05 5.232,19.558 23.673,19.558 24.867,20.752 27.178,20.752 28.372,21.946 29.718,21.946 31.344,23.571 v1(34.138,23.571)
  VCC w0.8: v2(11.913,58.42) 12.497,59.004 24.613,59.004 25.095,58.522 v2(27.153,58.522) 27.178,58.496 v2(42.393,58.496) 43.282,57.607 43.282,55.118 45.745,52.654 45.745,41.377 44.729,40.361 44.729,32.69 v2(46.901,30.518) 46.901,25.54 44.552,23.19 44.552,19.075 45.695,17.932 v2(47.015,17.932) 47.015,14.173 45.212,12.37 45.212,6.198 v2(46.863,4.547) 46.863,3.607 46.406,3.15 38.278,3.15 36.957,4.47 36.957,6.045 35.382,7.62 31.09,7.62 29.312,5.842 25.07,5.842 v2(24.054,6.858) 23.368,7.544 v2(18.237,7.544)
  Bottom Layer w0.3: R14.2@31.56,25.375 32.334,25.375 v1(34.138,23.571)
  Bottom Layer w0.6: M1.2@11.913,54.788 v2(11.913,58.42) ; M2.2@27.153,55.169 v2(27.153,58.522) ; M3.2@42.393,55.169 v2(42.393,58.496) ; M5.2@44.374,17.932 v2(47.015,17.932) ; M6.2@44.501,5.359 46.05,5.359 v2(46.863,4.547) ; M4.2@44.501,31.521 45.898,31.521 v2(46.901,30.518)
  other v2: 8.636,7.772 9.474,7.772 10.312,7.772 11.176,7.772 12.04,7.772 10.312,8.636 11.176,8.636
VOL_DETECT: R14.1 R15.2 U2.82 | length 7.8
  Top Layer w0.254: U2.82@24.136,24.33 27.201,24.33 v1(28.194,25.324)
  Bottom Layer w0.254: v1@28.169,25.349 30.06,25.349 R14.1@30.06,25.375 R15.2@30.06,26.772
VOL_LOW: LED1.2 U2.19 | length 39.8
  Top Layer w0.254: v1(3.2,57.3) LED1.2@4.6,58.7 ; v1(13.157,37.49) 13.157,37.44 13.586,37.011 U2.19@13.586,34.88
  Bottom Layer w0.254: v1(3.2,57.3) 3.1,57.2 3.1,52.577 3.683,51.994 3.683,40.234 4.521,39.395 4.521,34.849 5.893,33.477 9.093,33.477 10.719,35.103 12.573,35.103 13.157,35.687 v1(13.157,37.49)
VOUT: C1.2 C2.2 C6.2 C7.2 C18.2 C19.2 C20.2 C21.1 C22.1 C23.1 C27.2 C28.2 C29.2 C30.1 C31.1 C32.1 CP2.1 CP3.1 CP4.1 CP5.1 CP6.1 CP7.1 D1.1 Q1.1 Q1.2 Q1.3 U1.3 U7.4 U7.6 U7.11 U7.31 U9.4 U9.6 U9.11 U9.31 U10.4 U10.6 U10.11 U10.31 U16.4 U16.6 U16.11 U16.31 U17.4 U17.6 U17.11 U17.31 U18.4 U18.6 U18.11 U18.31 | length 80.7
  Top Layer w0.254: 34.4,37.4 34.491,37.4 ; 34.7,37.5 35.5,38.3 35.6,38.3
  Top Layer w0.3: D1.1@17.602,15.925 18.414,15.113 20.269,15.113 20.904,14.478 Q1.3@20.904,13.271
  Top Layer w0.6: 6.65,47.7 6.725,47.625 U7.4@8.568,47.625 ; 7,46.1 7.088,46.012 U7.6@8.568,46.012 ; CP3.1@8.797,56.693 6.553,56.693 5.563,55.702 5.563,54.674 8.941,54.674 9.601,54.014 9.601,53.365 10.668,52.298 U7.31@10.668,50.521 ; 10.516,41.377 10.668,41.529 U7.11@10.668,43.112 ; C20.2@20.752,54.674 23.812,54.674 24.625,53.861 24.625,52.972 25.299,52.298 U9.31@25.299,50.521 ; 21.6,46.1 21.688,46.012 U9.6@23.199,46.012 ; 21.7,47.6 21.725,47.625 U9.4@23.199,47.625 ; U9.11@25.299,43.112 25.299,41.749 25.316,41.732 ; CP6.1@32.614,24.731 34.587,24.731 v2(35.255,25.4) ; 35.6,46.1 35.713,45.987 U10.6@37.423,45.987 ; C18.2@35.916,54.674 37.389,54.674 38.442,54.674 39.116,54 39.116,52.603 39.523,52.197 U10.31@39.523,50.495 ; 36.1,7.3 36.166,7.366 U18.4@37.804,7.366 ; 36.1,19.1 36.112,19.088 U17.6@37.804,19.088 ; 36.1,47.6 U10.4@37.423,47.6 ; 36.3,20.6 36.401,20.701 U17.4@37.804,20.701 ; 36.3,32.7 36.323,32.677 U16.6@37.804,32.677 ; 36.39,34.29 U16.4@37.804,34.29 ; 36.4,5.8 36.447,5.753 U18.6@37.804,5.753 ; C27.2@37.504,40.411 38.71,40.411 39.904,39.217 U16.31@39.904,37.186 ; U10.11@39.523,43.087 39.523,41.072 39.649,40.945 ; 39.853,1.448 39.904,1.499 U18.11@39.904,2.853 ; 39.881,14.757 39.904,14.78 U17.11@39.904,16.188 ; U18.31@39.904,10.262 39.904,11.676 39.911,11.684 ; U17.31@39.904,23.597 39.904,25.451 ; U16.11@39.904,29.777 39.904,28.242 39.926,28.219
  Bottom Layer w0.6: v2(35.255,12.827) 35.281,12.852 C32.1@36.258,12.852 C29.2@36.258,11.43 ; v2(35.255,25.4) C31.1@36.105,26.25 ; C28.2@36.105,24.917 C31.1@36.105,26.25 ; C31.1@36.105,26.34 C31.1@36.105,26.25 ; C30.1@37.326,38.989 37.998,38.989 v2(38.354,39.345)
pads on no net: JC1.4 JC1.6 JC1.7 M1.6 M1.7 M2.6 M2.7 M3.6 M3.7 M4.6 M4.7 M5.6 M5.7 M6.6 M6.7 RESET.3 RESET.4 U2.4 U2.8 U2.9 U2.14 U2.23 U2.26 U2.27 U2.28 U2.29 U2.35 U2.36 U2.37 U2.38 U2.39 U2.40 U2.41 U2.42 U2.47 U2.48 U2.49 U2.51 U2.52 U2.55 U2.56 U2.57 U2.58 U2.59 U2.60 U2.63 U2.64 U2.65 U2.66 U2.67 U2.68 U2.69 U2.72 U2.73 U2.76 U2.77 U2.78 U2.79 U3.3 U3.6 U3.8 U3.9 U3.10 U3.11 U3.12 U3.13 U3.14 U3.24 U3.27 U3.28 U7.7 U7.9 U7.17 U7.21 U7.25 U9.7 U9.9 U9.17 U9.21 U9.25 U10.7 U10.9 U10.17 U10.21 U10.25 U16.7 U16.9 U16.17 U16.21 U16.25 U17.7 U17.9 U17.17 U17.21 U17.25 U18.7 U18.9 U18.17 U18.21 U18.25

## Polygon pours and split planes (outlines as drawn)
VOUT on Top Layer "Top Layer-No Net" (solid, remove dead copper, pour order 11): 0,0 48.641,0 48.641,60.198 0,60.198
VIN on Top Layer "Top Layer-No Net" (solid, remove dead copper, pour order 8): 11.125,5 11.125,4.191 23.292,4.191 24.663,5.563 24.714,5.613 24.714,8.661 24.714,9.779 24.359,10.135 24.206,10.287 20.98,10.287 1.549,10.287 0,8.738 0,5
GND on GND "Top Layer-No Net" (solid, remove dead copper, pour order 9): 0.076,0.025 0.076,60.122 0,60.198 48.641,60.198 48.641,0
5VD on VCC "Top Layer-No Net" (solid, remove dead copper, pour order 12): 0,0 48.641,0 48.641,60.198 0,60.198
no net on VCC "Top Layer-No Net" (none, remove dead copper, pour order 10): 9.461,0 cw(c9.525,0)

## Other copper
Top Layer:
  region net M1B: 11.163,41.631 11.443,41.91 13.856,41.91 14.173,41.592 14.173,40.094 13.932,39.853 11.366,39.853 11.163,40.056
  region net M1A: 11.176,52.222 11.227,52.781 11.532,53.137 13.513,53.137 14.173,52.476 14.173,51.74 11.328,51.74 11.176,51.892
  region net M2A: 25.806,52.222 25.857,52.781 26.162,53.137 28.143,53.137 28.804,52.476 28.804,51.74 25.959,51.74 25.806,51.892
  region net M2B: 25.794,41.631 26.073,41.91 28.486,41.91 28.804,41.592 28.804,40.615 28.296,40.107 26.086,40.107 25.794,40.399
  region net M3A: 40.03,52.197 40.081,52.756 40.386,53.111 42.367,53.111 43.028,52.451 43.028,51.714 40.183,51.714 40.03,51.867
  region net M5A: 40.411,25.298 40.462,25.857 40.767,26.213 42.748,26.213 43.409,25.552 43.409,24.816 40.564,24.816 40.411,24.968
  region net M4A: 40.424,38.659 40.457,39.021 40.996,39.649 42.685,39.649 43.421,38.913 43.421,38.583 40.424,38.583
  region net M6A: 40.389,11.887 40.389,12.225 40.578,12.446 42.854,12.446 43.409,11.891 43.409,11.43 40.513,11.43 40.389,11.582
  region net M6B: 43.431,1.295 43.431,0.957 43.242,0.737 40.742,0.737 40.411,1.067 40.411,1.753 43.307,1.753 43.431,1.6
  region net VIN: 9.525,0 7.747,0 7.747,6.833 8.153,7.239 12.446,7.239 12.903,6.833 12.903,0 11.125,0 11.125,5 9.525,5
  region net GND: 6.35,6.35 6.35,8.611 5.791,9.169 2.667,9.169 2.108,8.611 2.108,6.35
  region net VIN: 12.421,6.223 12.421,8.484 11.862,9.042 8.738,9.042 8.179,8.484 8.179,6.223
VCC:
  pour cut-out: 9.525,0 9.525,5 11.125,5 11.125,0
GND:
  pour cut-out: 9.525,0 9.525,5 11.125,5 11.125,0
Bottom Layer:
  region net M4B: 42.843,28.124 42.843,27.502 42.602,27.261 40.773,27.261 40.519,27.515 40.519,28.34 40.761,28.581 42.666,28.581 42.843,28.416 42.843,28.226
  region net M1B: 11.163,41.631 11.443,41.91 13.856,41.91 14.173,41.592 14.173,40.094 13.932,39.853 11.366,39.853 11.163,40.056
  region net M2B: 25.794,41.631 26.073,41.91 27.838,41.91 28.092,41.656 28.092,40.64 27.752,40.3 26,40.3 25.794,40.506
  region net M3B: 40.919,42.266 42.418,42.266 42.799,41.808 42.799,41.148 42.672,41.021 40.437,41.021 40.259,41.199 40.259,41.275 40.259,41.605
  region net M4A: 40.843,39.04 40.843,39.573 40.97,39.7 42.901,39.7 43.053,39.548 43.053,38.456 42.926,38.329 41,38.329 40.843,38.474 40.843,38.938
  region net M5B: 43.066,14.199 43.066,13.665 42.939,13.538 41.008,13.538 40.856,13.691 40.856,14.529 40.983,14.656 42.888,14.656 43.066,14.491 43.066,14.3
  region net M6A: 43.142,12.065 43.142,11.443 42.901,11.201 41.072,11.201 40.818,11.455 40.818,12.281 41.059,12.522 42.964,12.522 43.142,12.357 43.142,12.167
  region net M5A: 42.761,25.756 42.761,25.133 42.52,24.892 40.691,24.892 40.437,25.146 40.437,25.972 40.678,26.213 42.583,26.213 42.761,26.048 42.761,25.857
  region net M6B: 42.913,1.168 42.913,1.791 42.672,2.032 40.843,2.032 40.589,1.778 40.589,0.953 40.831,0.711 42.735,0.711 42.913,0.876 42.913,1.067
  region net VIN: 9.525,0 7.747,0 7.747,6.833 8.153,7.239 12.446,7.239 12.903,6.833 12.903,0 11.125,0 11.125,5 9.525,5
  region net GND: 2.184,6.35 2.184,8.611 2.743,9.169 5.867,9.169 6.426,8.611 6.426,6.35
  region net VIN: 8.204,6.223 8.204,8.484 8.763,9.042 11.887,9.042 12.446,8.484 12.446,6.223

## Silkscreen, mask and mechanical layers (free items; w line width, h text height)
Top Overlay:
  text "LOW POWER" at 3.5,57 h0.8
  text "GND    5V    RESET    SCK    MOSI   MISO" at 3.4,54.4 h0.8 r270
  text "A4->6" at 3.429,39.243 h0.76 r270
Bottom Overlay:
  text "-" at 4.496,8.992 h3
  text "+" at 10.947,8.763 h3
Top Solder:
  region: 9.525,0 7.747,0 7.747,6.833 8.153,7.239 12.446,7.239 12.903,6.833 12.903,0 11.125,0 11.125,5 9.525,5
Bottom Solder:
  region: 9.525,0 7.747,0 7.747,6.833 8.153,7.239 12.446,7.239 12.903,6.833 12.903,0 11.125,0 11.125,5 9.525,5
Mechanical 1:
  lines w0.013: 7.214,-6.833 9.423,-2.007 ; 9.042,-2.261 9.423,-2.007 ; 9.5,-2.438 9.423,-2.007
  lines w0.127: 0,0 6.452,0 9.525,0 48.641,0 48.641,60.198 0,60.198 0,0
  text "PTH" at 10.338,-3.734 h1.52
Mechanical 6:
  lines w0.127: 0,-0.127 0,60.198 48.641,60.198 48.641,-0.127 0,-0.127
